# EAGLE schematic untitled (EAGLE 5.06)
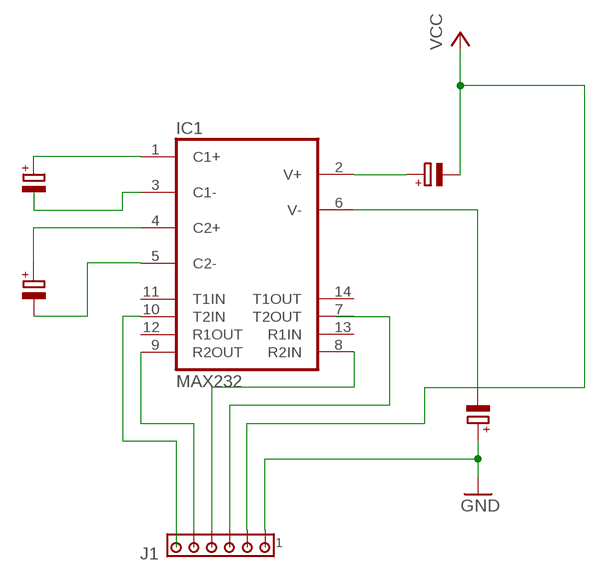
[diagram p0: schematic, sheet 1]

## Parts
IC1  MAX232  [DIL16]
J1  MTA06-100  [10X06MTA]

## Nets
GND: J1.6
N$1: IC1.1(C1+)
N$2: IC1.3(C1-)
N$3: IC1.4(C2+)
N$4: IC1.5(C2-)
N$5: IC1.6(V-)
N$6: IC1.2(V+)
N$7: IC1.8(R2IN) J1.3
N$9: J1.4
N$10: IC1.9(R2OUT) J1.2
N$11: IC1.10(T2IN)
VCC: J1.5
Unconnected: IC1.7(T2OUT) IC1.11(T1IN) IC1.12(R1OUT) IC1.13(R1IN) IC1.14(T1OUT) J1.1

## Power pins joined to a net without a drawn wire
GND: IC1.15(GND)
VCC: IC1.16(VCC)

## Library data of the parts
IC1 = maxim:MAX232: RS232 TRANSEIVER
J1 = con-amp:MTA06-100: AMP connector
